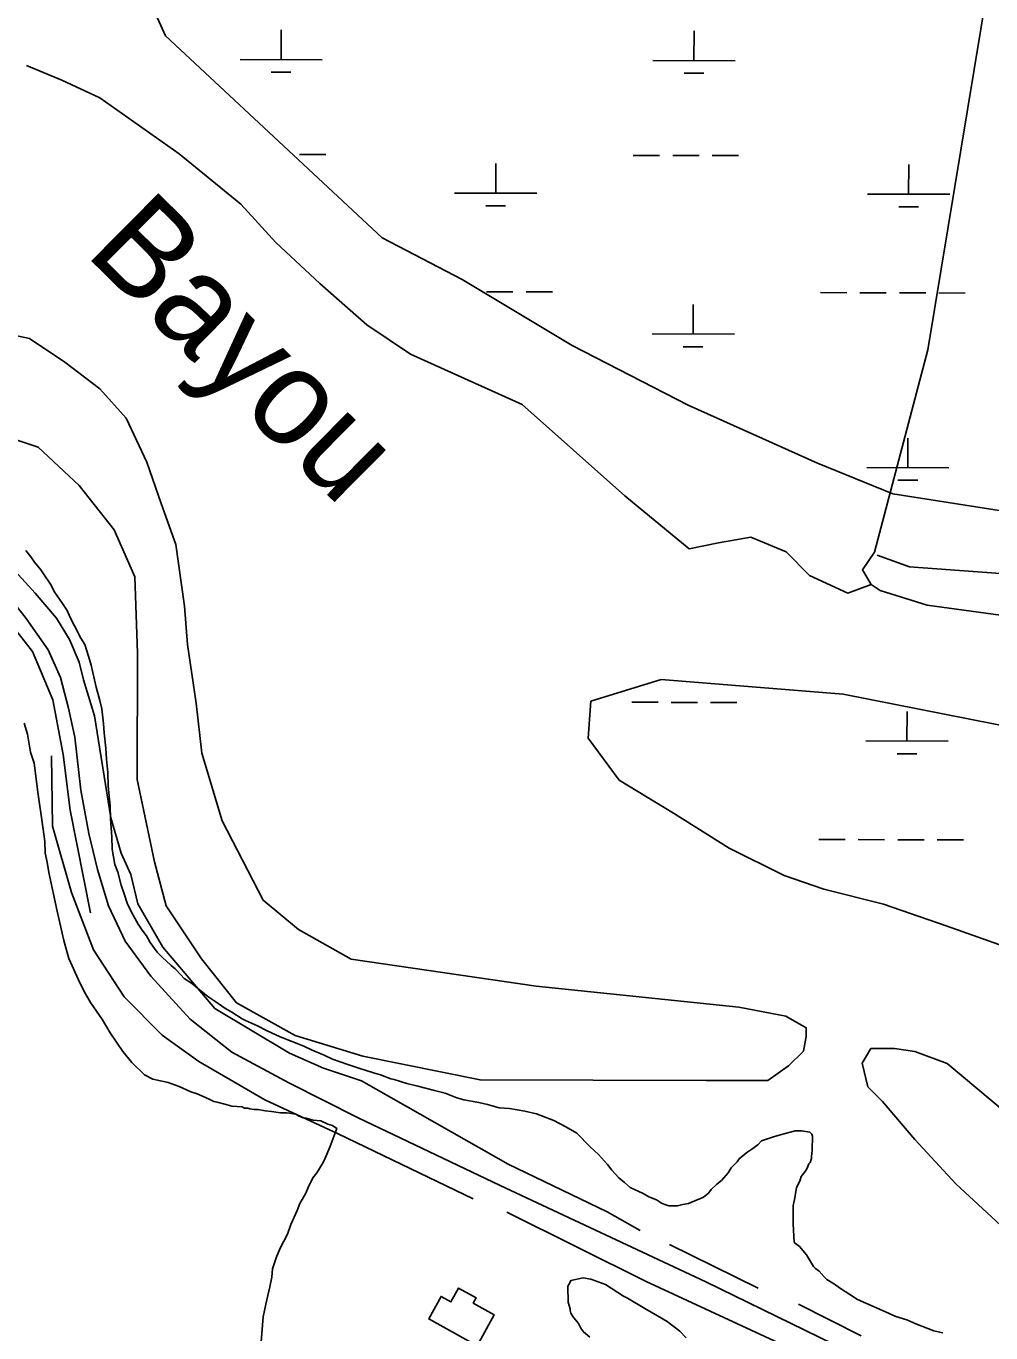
# Model space of a CAD drawing. Extents: x 3172297 to 3210190, y 958463 to 983887.
# Drawn here: x 3179951 to 3181124, y 979111 to 980700 of the extents above; entities that cross this region are included whole.
import ezdxf

# ---------------------------------------------------------------- set-up
doc = ezdxf.new("R2010")
doc.units = 0
for name, color, linetype in [('V-BLDG-OTLN', 7, 'Continuous'), ('V-RIVR-IDEN', 7, 'Continuous'), ('V-ROAD-CNTR', 7, 'Continuous'), ('V-SITE-VEGE', 7, 'Continuous'), ('V-TOPO-SHOR', 7, 'Continuous'), ('V-WETL-SWMP', 7, 'Continuous')]:
    doc.layers.add(name, color=color, linetype=linetype)

msp = doc.modelspace()

# ---------------------------------------------------------------- linework, layer by layer
at = {"layer": 'V-BLDG-OTLN'}
msp.add_lwpolyline([(3180499.7, 979095.2), (3180440.7, 979127.9), (3180455.8, 979155.3), (3180467.8, 979148.6), (3180477.1, 979165.4), (3180498.4, 979153.6), (3180494.8, 979147.1), (3180520.5, 979132.8)], close=True, dxfattribs=at)
at = {"layer": 'V-ROAD-CNTR'}
msp.add_lwpolyline([(3180984.4, 979071.9), (3180777.6, 979173), (3180527.6, 979290.2), (3180355, 979372.5), (3180270.7, 979414.8), (3180201.6, 979452.1), (3180150.9, 979492.5), (3180102.8, 979544.4), (3180071.8, 979587.1), (3180051.4, 979630.1), (3180038, 979674.2), (3180027.4, 979718.1), (3180018, 979770.7), (3180010.6, 979835.2), (3180002.7, 979870.4), (3179993, 979907.7), (3179978, 979941.3), (3179951.4, 979979.6), (3179917.8, 980022.1)], dxfattribs=at)
at = {"layer": 'V-SITE-VEGE'}
for p, q in [((3179957, 980054.3), (3179950.8, 980062.2)), ((3179961.6, 980048.1), (3179957, 980054.3)), ((3179969.4, 980038.6), (3179961.6, 980048.1)), ((3179973.2, 980032.4), (3179969.4, 980038.6)), ((3179981, 980021.4), (3179973.2, 980032.4)), ((3179986.4, 980011.2), (3179981, 980021.4)), ((3179995.6, 979997.9), (3179986.4, 980011.2)), ((3180001.1, 979989.2), (3179995.6, 979997.9)), ((3180004.9, 979980.6), (3180001.1, 979989.2)), ((3180010.3, 979970.4), (3180004.9, 979980.6)), ((3180018, 979955.6), (3180010.3, 979970.4)), ((3180022.6, 979947.7), (3180018, 979955.6)), ((3180027.2, 979933.6), (3180022.6, 979947.7)), ((3180030.3, 979922.7), (3180027.2, 979933.6)), ((3180036.4, 979896.1), (3180030.3, 979922.7)), ((3180040.9, 979879.7), (3180036.4, 979896.1)), ((3180043.2, 979869.5), (3180040.9, 979879.7)), ((3180045.4, 979851.5), (3180043.2, 979869.5)), ((3180046.1, 979840.6), (3180045.4, 979851.5)), ((3180048.4, 979821.8), (3180046.1, 979840.6)), ((3180049.1, 979808.6), (3180048.4, 979821.8)), ((3180050.5, 979792.2), (3180049.1, 979808.6)), ((3180051.2, 979775.8), (3180050.5, 979792.2)), ((3180053.4, 979751.6), (3180051.2, 979775.8)), ((3180054, 979735.9), (3180053.4, 979751.6)), ((3180055.5, 979714.1), (3180054, 979735.9)), ((3180056.1, 979699.2), (3180055.5, 979714.1)), ((3180059.1, 979680.5), (3180056.1, 979699.2)), ((3180063, 979671.1), (3180059.1, 979680.5)), ((3180066.8, 979655.4), (3180063, 979671.1)), ((3180070.6, 979644.5), (3180066.8, 979655.4)), ((3180074.4, 979632), (3180070.6, 979644.5)), ((3180081.4, 979618.6), (3180074.4, 979632)), ((3180087.5, 979607.7), (3180081.4, 979618.6)), ((3180092.2, 979600.6), (3180087.5, 979607.7)), ((3180097.6, 979593.5), (3180092.2, 979600.6)), ((3180102.2, 979585.7), (3180097.6, 979593.5)), ((3180110.7, 979573.9), (3180102.2, 979585.7)), ((3180116.9, 979567.7), (3180110.7, 979573.9)), ((3180127.8, 979557.4), (3180116.9, 979567.7)), ((3180132.5, 979553.5), (3180127.8, 979557.4)), ((3180139.4, 979546.4), (3180132.5, 979553.5)), ((3180143.3, 979541.7), (3180139.4, 979546.4)), ((3180153.4, 979535.4), (3180143.3, 979541.7)), ((3180159.6, 979529.9), (3180153.4, 979535.4)), ((3180172.1, 979519.7), (3180159.6, 979529.9)), ((3180180.6, 979514.1), (3180172.1, 979519.7)), ((3180193, 979505.5), (3180180.6, 979514.1)), ((3180201.6, 979500.7), (3180193, 979505.5)), ((3180214, 979492.8), (3180201.6, 979500.7)), ((3180217.9, 979490.5), (3180214, 979492.8)), ((3180232.7, 979484.1), (3180217.9, 979490.5)), ((3180243.6, 979478.6), (3180232.7, 979484.1)), ((3180260, 979470.7), (3180243.6, 979478.6)), ((3180288.8, 979459.6), (3180260, 979470.7)), ((3180298.9, 979454.8), (3180288.8, 979459.6)), ((3180313.7, 979448.5), (3180298.9, 979454.8)), ((3180323.8, 979443.7), (3180313.7, 979448.5)), ((3180342.5, 979437.3), (3180323.8, 979443.7)), ((3180355.7, 979432.6), (3180342.5, 979437.3)), ((3180373.7, 979427), (3180355.7, 979432.6)), ((3180382.2, 979424.6), (3180373.7, 979427)), ((3180394.7, 979419.8), (3180382.2, 979424.6)), ((3180398.6, 979419), (3180394.7, 979419.8)), ((3180414.2, 979414.2), (3180398.6, 979419)), ((3180427.4, 979411), (3180414.2, 979414.2)), ((3180447.7, 979405.4), (3180427.4, 979411)), ((3180460.9, 979402.2), (3180447.7, 979405.4)), ((3180474.9, 979396.7), (3180460.9, 979402.2)), ((3180483.5, 979394.2), (3180474.9, 979396.7)), ((3180501.5, 979391), (3180483.5, 979394.2)), ((3180512.4, 979388.6), (3180501.5, 979391)), ((3180526.4, 979384.6), (3180512.4, 979388.6)), ((3180538.9, 979383.7), (3180526.4, 979384.6)), ((3180557.6, 979380.5), (3180538.9, 979383.7)), ((3180571.6, 979377.3), (3180557.6, 979380.5)), ((3180592.7, 979369.3), (3180571.6, 979377.3)), ((3180607.4, 979361.4), (3180592.7, 979369.3)), ((3180620.7, 979353.5), (3180607.4, 979361.4)), ((3180636.9, 979337), (3180620.7, 979353.5)), ((3180871.3, 979352.6), (3180861.1, 979349.6)), ((3180886.1, 979356.5), (3180871.3, 979352.6)), ((3180893.9, 979356.4), (3180886.1, 979356.5)), ((3180904.1, 979354.8), (3180893.9, 979356.4)), ((3180906.4, 979352.4), (3180904.1, 979354.8)), ((3180907.2, 979350.1), (3180906.4, 979352.4)), ((3180647, 979327.6), (3180636.9, 979337)), ((3180840.7, 979339.6), (3180833.7, 979334.2)), ((3180845.5, 979344.2), (3180840.7, 979339.6)), ((3180861.1, 979349.6), (3180845.5, 979344.2)), ((3180907.1, 979332.9), (3180907.2, 979350.1)), ((3180657.9, 979315.8), (3180647, 979327.6)), ((3180818, 979322.6), (3180815.6, 979318.7)), ((3180827.4, 979330.3), (3180818, 979322.6)), ((3180833.7, 979334.2), (3180827.4, 979330.3)), ((3180904.6, 979318.1), (3180906.2, 979322.8)), ((3180906.2, 979325.1), (3180907.1, 979332.9)), ((3180906.2, 979322.8), (3180906.2, 979325.1)), ((3180663.3, 979308.7), (3180657.9, 979315.8)), ((3180671.8, 979299.3), (3180663.3, 979308.7)), ((3180804.6, 979305.5), (3180796.7, 979296.1)), ((3180808.5, 979311.7), (3180804.6, 979305.5)), ((3180815.6, 979318.7), (3180808.5, 979311.7)), ((3180893.6, 979301), (3180898.3, 979307.2)), ((3180898.3, 979307.2), (3180900.7, 979311.1)), ((3180900.7, 979311.1), (3180903, 979316.5)), ((3180903, 979316.5), (3180904.6, 979318.1)), ((3180678.8, 979293.8), (3180671.8, 979299.3)), ((3180685.8, 979287.5), (3180678.8, 979293.8)), ((3180791.2, 979291.5), (3180784.2, 979285.3)), ((3180796.7, 979296.1), (3180791.2, 979291.5)), ((3180888, 979287.7), (3180892, 979295.5)), ((3180892, 979295.5), (3180893.6, 979301)), ((3180701.4, 979280.4), (3180685.8, 979287.5)), ((3180708.4, 979276.4), (3180701.4, 979280.4)), ((3180717.7, 979272.5), (3180708.4, 979276.4)), ((3180723.9, 979268.5), (3180717.7, 979272.5)), ((3180774.7, 979276), (3180756.7, 979268.3)), ((3180781, 979280.6), (3180774.7, 979276)), ((3180784.2, 979285.3), (3180781, 979280.6)), ((3180884, 979265.9), (3180885.6, 979272.9)), ((3180885.6, 979272.9), (3180887.2, 979282.3)), ((3180887.2, 979282.3), (3180888, 979287.7)), ((3180727.8, 979266.9), (3180723.9, 979268.5)), ((3180732.5, 979265.3), (3180727.8, 979266.9)), ((3180743.4, 979265.3), (3180732.5, 979265.3)), ((3180749.7, 979266.8), (3180743.4, 979265.3)), ((3180756.7, 979268.3), (3180749.7, 979266.8)), ((3180883.8, 979243.3), (3180884, 979265.9)), ((3180885.2, 979220.6), (3180883.8, 979243.3)), ((3180891.4, 979215.9), (3180885.2, 979220.6)), ((3180900, 979205.7), (3180891.4, 979215.9)), ((3180908.5, 979191.6), (3180900, 979205.7)), ((3180910.8, 979189.2), (3180908.5, 979191.6)), ((3180915.5, 979186.1), (3180910.8, 979189.2)), ((3180921.7, 979179), (3180915.5, 979186.1)), ((3180924.8, 979175.8), (3180921.7, 979179)), ((3180934.1, 979170.3), (3180924.8, 979175.8)), ((3180940.3, 979165.6), (3180934.1, 979170.3)), ((3180952.7, 979157.7), (3180940.3, 979165.6)), ((3180962.1, 979151.4), (3180952.7, 979157.7)), ((3180992.4, 979137.9), (3180962.1, 979151.4)), ((3181008.8, 979130.8), (3180992.4, 979137.9)), ((3181022, 979126.8), (3181008.8, 979130.8)), ((3181032.9, 979122), (3181022, 979126.8)), ((3181054.7, 979113.3), (3181032.9, 979122)), ((3181065.6, 979110.9), (3181054.7, 979113.3))]:
    msp.add_line(p, q, dxfattribs=at)
for points in [[(3179949.1, 979852), (3179952.9, 979838.7), (3179956.7, 979816.9), (3179961.3, 979803.6), (3179965.7, 979768.4), (3179971.7, 979726.2), (3179973.9, 979708.2), (3179974.6, 979694.2), (3179976.9, 979683.2), (3179979.1, 979670.7), (3179989, 979623.8), (3179997.3, 979587.8), (3180003.4, 979565.9), (3180015, 979540.1), (3180021.9, 979526), (3180029.6, 979512.7), (3180044.3, 979491.5), (3180053.6, 979475.8), (3180069, 979453.1), (3180079.9, 979439.7), (3180095.4, 979424.8), (3180105.5, 979419.3), (3180124.2, 979415.2), (3180137.5, 979410.5), (3180151.5, 979404.1), (3180159.3, 979401.7), (3180169.4, 979397), (3180174.8, 979394.6), (3180179.5, 979392.2), (3180183.4, 979391.4), (3180192.7, 979389), (3180201.3, 979386.6), (3180213.8, 979385.8), (3180216.9, 979384.2), (3180220.8, 979384.1), (3180223.2, 979383.3), (3180228.6, 979382.5), (3180233.3, 979382.5), (3180241.9, 979380.9), (3180249.7, 979380.1), (3180260.6, 979378.4), (3180268.4, 979378.4), (3180279.3, 979376.7), (3180281.7, 979375.2), (3180287.1, 979372.8), (3180291.8, 979372), (3180300.4, 979369.6), (3180309.7, 979368.7), (3180318.3, 979364.8), (3180323.7, 979363.2), (3180329.2, 979359.2), (3180320.4, 979336.6), (3180314.9, 979323.4), (3180312.5, 979318), (3180304.6, 979305.5), (3180299.9, 979299.3), (3180294.4, 979287.6), (3180291.2, 979280.6), (3180284.1, 979268.2), (3180280.9, 979259.6), (3180273, 979242.5), (3180269, 979230.8), (3180260.3, 979213.7), (3180255.5, 979202), (3180250.8, 979188.8), (3180249.9, 979178.6), (3180247.5, 979166.9), (3180242.7, 979145.9), (3180239.4, 979130.3), (3180236.9, 979099.8)], [(3180636.7, 979105.8), (3180628.9, 979112.1), (3180625.8, 979116.8), (3180622.7, 979122.3), (3180615.8, 979130.9), (3180613.4, 979134.8), (3180612.7, 979138), (3180612.7, 979140.3), (3180610.4, 979148.1), (3180610.4, 979153.6), (3180609.7, 979162.2), (3180609.8, 979167.7), (3180612.1, 979170.8), (3180613.7, 979174.7), (3180628.6, 979177.7), (3180637.9, 979176.1), (3180655.8, 979169.7), (3180677.6, 979155.5), (3180682.3, 979153.1), (3180703.3, 979140.5), (3180718.8, 979131.8), (3180730.5, 979124.7), (3180746, 979112.9), (3180753.8, 979105)]]:
    msp.add_lwpolyline(points, dxfattribs=at)
at = {"layer": 'V-TOPO-SHOR'}
for p, q in [((3180733.5, 979218.4), (3180841.4, 979165.4)), ((3180890.5, 979145.7), (3180966.3, 979107.1))]:
    msp.add_line(p, q, dxfattribs=at)
for points in [[(3182796.9, 980191.3), (3182361, 980110.2), (3182150.2, 980057.2), (3181939.3, 979993.4), (3181807.1, 979954.5), (3181660.7, 979944.1), (3181260.8, 979966.6), (3181046.6, 979995.7), (3180989.5, 980013.6), (3180978.8, 980020.8), (3180968.1, 980038.7), (3180982.5, 980060.1), (3181047.4, 980306.3), (3181119.9, 980745.4), (3181173.7, 980863.1), (3181238.3, 980970.1), (3181299.2, 981059.2), (3181352.9, 981134.1), (3181428.2, 981244.6), (3181471.2, 981312.3), (3181524.9, 981358.6)], [(3180978.8, 980020.8), (3180950.2, 980010.2), (3180903.8, 980031.7), (3180875.3, 980060.4), (3180832.5, 980078.3), (3180793.2, 980071.3), (3180757.5, 980064.2), (3180679.1, 980128.7), (3180554.4, 980239.7), (3180418.8, 980300.7), (3180365.4, 980336.6), (3180308.3, 980386.7), (3180254.9, 980436.8), (3180212.2, 980483.4), (3180137.3, 980544.3), (3180041.1, 980612.4), (3179994.7, 980633.9), (3179951.9, 980651.9)], [(3179858.9, 980223.6), (3179965.9, 980187.6), (3180015.8, 980141), (3180058.5, 980087.4), (3180083.4, 980030.2), (3180086.7, 979937.3), (3180086.3, 979783.8), (3180107.5, 979683.7), (3180121.7, 979630.1), (3180164.4, 979565.7), (3180207.1, 979512.1), (3180278.4, 979472.6), (3180360.5, 979447.4), (3180503.3, 979418.5), (3180778.2, 979417.8), (3180853.2, 979417.6), (3180878.3, 979435.4), (3180896.2, 979453.2), (3180899.8, 979471.1), (3180899.8, 979481.8), (3180874.8, 979496.1), (3180817.7, 979507), (3180571.4, 979532.6), (3180346.5, 979565.3), (3180282.3, 979601.2), (3180239.5, 979637), (3180189.8, 979733.5), (3180165, 979815.7), (3180158, 979876.4), (3180147.5, 979947.9), (3180144, 979994.3), (3180133.5, 980069.3), (3180115.7, 980119.4), (3180098, 980169.4), (3180073.1, 980223), (3180041.1, 980258.8), (3179998.3, 980291.1), (3179955.5, 980319.7), (3179905.6, 980330.6)], [(3180986, 980056.5), (3181025.3, 980042.1), (3181428.7, 980012.6), (3181753.7, 980004.6), (3181928.8, 980043.5), (3182132.4, 980100.1), (3182261.1, 980142.6), (3182400.5, 980174.4), (3182797, 980241.3)], [(3179756.4, 980104.6), (3179809.9, 980100.9), (3179851, 980092.8), (3179884, 980079.3), (3179929.4, 980046.2), (3179962.4, 980010.4), (3179988.2, 979980), (3180004.2, 979954), (3180015.7, 979926.3), (3180021, 979904.9), (3180034.3, 979861.1), (3180054.5, 979737), (3180066.9, 979694.1), (3180078.5, 979668.2), (3180087.3, 979632.4), (3180117.5, 979579.7), (3180180.7, 979505.4), (3180271.7, 979450.8), (3180312.7, 979432.8), (3180359.1, 979417.5), (3180537.4, 979316.2), (3180657.8, 979257.9), (3180697.9, 979235.4)], [(3180029.7, 979621.4), (3180005, 979746.5), (3179996.3, 979814.3), (3179983.9, 979880.4), (3179959.1, 979939.4), (3179918.1, 979991.3), (3179891.4, 980012.8), (3179855.7, 980037.9), (3179832.6, 980046.9), (3179818.3, 980045.1), (3179798.6, 980045.2)], [(3180494.9, 979273.9), (3180330.8, 979352.8), (3180241.6, 979394.1), (3180161.4, 979440.8), (3180116.8, 979473), (3180070.5, 979519.5), (3180033.2, 979576.8), (3180006.6, 979646.5), (3179983.5, 979726.9), (3179982, 979812.6)], [(3181466.7, 979109), (3181420.3, 979130.5), (3181331.2, 979195), (3181227.9, 979288.1), (3181178, 979349), (3181071.1, 979438.5), (3181031.9, 979452.9), (3181006.9, 979456.5), (3180978.3, 979456.6), (3180967.5, 979438.8), (3180974.6, 979410.2), (3180992.4, 979392.3), (3181031.6, 979345.8), (3181081.5, 979292.1), (3181256, 979130.9), (3181388, 979044.9)], [(3182097.9, 978423.6), (3181935.7, 978534.7), (3181739.6, 978663.7), (3181613.1, 978740.8), (3181449, 978828.7), (3181333.1, 978882.6), (3180960.3, 979054.9), (3180705.3, 979173.4), (3180535.9, 979257.7)]]:
    msp.add_lwpolyline(points, dxfattribs=at)
at = {"layer": 'V-WETL-SWMP'}
for p, q in [((3180120.6, 980687.9), (3180036.9, 980874)), ((3180384.3, 980442.2), (3180120.6, 980687.9)), ((3180261.4, 980659.1), (3180261.5, 980695)), ((3180763.2, 980657.8), (3180763.3, 980693.8)), ((3180211.4, 980659.2), (3180311.4, 980658.9)), ((3180713.2, 980657.9), (3180813.2, 980657.7)), ((3180249.3, 980643.7), (3180273.3, 980643.6)), ((3180751.2, 980642.4), (3180775.2, 980642.4)), ((3180283.6, 980543.6), (3180315.6, 980543.6)), ((3180522.3, 980496.6), (3180522.4, 980532.6)), ((3180689.5, 980542.6), (3180721.5, 980542.6)), ((3180737.5, 980542.5), (3180769.5, 980542.4)), ((3180785.5, 980542.4), (3180817.5, 980542.3)), ((3181024.2, 980495.4), (3181024.3, 980531.4)), ((3180472.3, 980496.8), (3180572.3, 980496.5)), ((3180974.2, 980495.5), (3181074.2, 980495.3)), ((3180510.3, 980481.3), (3180534.3, 980481.2)), ((3181012.1, 980480), (3181036.1, 980480)), ((3180481.5, 980391.7), (3180384.3, 980442.2)), ((3180615.2, 980311.3), (3180481.5, 980391.7)), ((3180511.1, 980376.7), (3180543.1, 980376.6)), ((3180559.1, 980376.5), (3180591.1, 980376.5)), ((3180917, 980375.7), (3180949, 980375.6)), ((3180965, 980375.5), (3180997, 980375.5)), ((3181013, 980375.4), (3181045, 980375.3)), ((3181061, 980375.3), (3181093, 980375.2)), ((3180762.3, 980325.3), (3180762.4, 980361.3)), ((3180712.3, 980325.5), (3180812.3, 980325.2)), ((3180756, 980238.7), (3180615.2, 980311.3)), ((3180750.2, 980309.9), (3180774.2, 980309.9)), ((3180913.2, 980168.3), (3180756, 980238.7)), ((3181023.2, 980162.9), (3181023.3, 980198.9)), ((3181005, 980131.1), (3180913.2, 980168.3)), ((3180973.2, 980163), (3181073.2, 980162.8)), ((3181011.2, 980147.5), (3181035.2, 980147.5)), ((3181171.1, 980105.1), (3181005, 980131.1)), ((3180637.9, 979879.1), (3180723.2, 979905.1)), ((3180723.2, 979905.1), (3180944.8, 979887.4)), ((3180634.5, 979833.9), (3180637.9, 979879.1)), ((3180687.6, 979877.7), (3180719.5, 979877.6)), ((3180735.5, 979877.5), (3180767.5, 979877.5)), ((3180783.5, 979877.4), (3180815.5, 979877.3)), ((3180944.8, 979887.4), (3181258.1, 979825.4)), ((3181022.2, 979830.4), (3181022.3, 979866.4)), ((3180672.4, 979783), (3180634.5, 979833.9)), ((3180972.2, 979830.6), (3181072.2, 979830.3)), ((3181010.2, 979815), (3181034.2, 979815)), ((3180738.4, 979742.8), (3180672.4, 979783)), ((3180806, 979700.3), (3180738.4, 979742.8)), ((3180915, 979710.7), (3180947, 979710.6)), ((3180963, 979710.6), (3180995, 979710.5)), ((3181011, 979710.5), (3181043, 979710.4)), ((3181059, 979710.3), (3181091, 979710.3)), ((3180872.9, 979667.1), (3180806, 979700.3)), ((3180921.2, 979650.4), (3180872.9, 979667.1)), ((3180993.7, 979632.1), (3180921.2, 979650.4)), ((3181070, 979605.9), (3180993.7, 979632.1)), ((3181172.8, 979569.4), (3181070, 979605.9))]:
    msp.add_line(p, q, dxfattribs=at)

# ---------------------------------------------------------------- texts
at = {"layer": 'V-RIVR-IDEN'}
msp.add_text('Bayou', height=116, rotation=315.2414, dxfattribs=at).set_placement((3180021.4, 980423.2))

doc.saveas('drawing.dxf')
